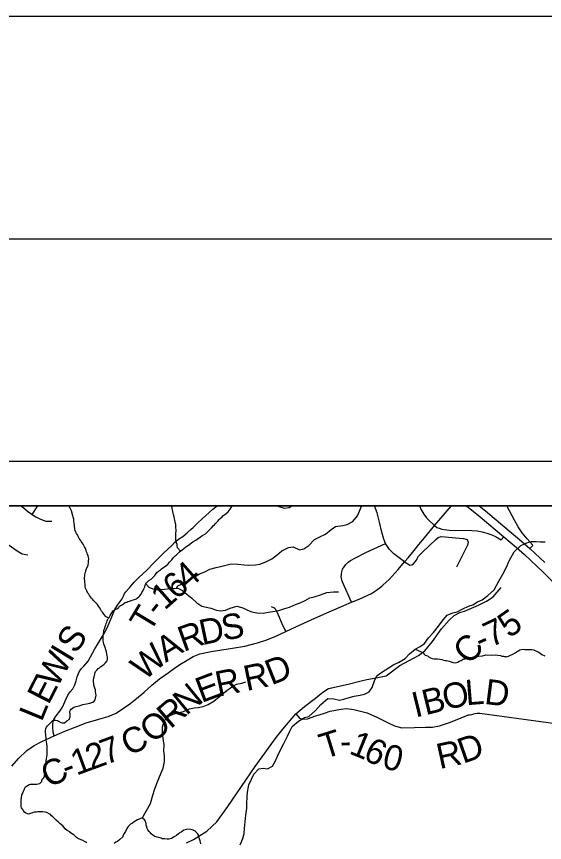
# Model space of a CAD drawing. Extents: x 44.2 to 78.2, y 4.5 to 26.5.
# Drawn here: x 49.173 to 50.361, y 24.644 to 26.501 of the extents above; entities that cross this region are included whole.
import ezdxf

# ---------------------------------------------------------------- set-up
doc = ezdxf.new("R2010")
doc.units = 0
for name, color, linetype in [('GM_X_County_Road', 7, 'Continuous'), ('GM_X_County_Road_Text', 7, 'Continuous'), ('GM_X_Interchange_Ramps', 7, 'Continuous'), ('GM_X_Interstate_Route', 7, 'Continuous'), ('GM_X_Minor_River', 7, 'Continuous'), ('GM_X_Rail_Line', 7, 'Continuous'), ('GM_X_Township_Road', 7, 'Continuous'), ('GM_X_Township_Road_Text', 7, 'Continuous'), ('SH_Border', 7, 'Continuous'), ('SH_Cut_Line', 7, 'Continuous'), ('SH_Data', 7, 'Continuous')]:
    doc.layers.add(name, color=color, linetype=linetype)

msp = doc.modelspace()

# ---------------------------------------------------------------- linework, layer by layer
at = {"layer": 'GM_X_County_Road'}
msp.add_line((50.1134, 25.3565), (50.1514, 25.4014), dxfattribs=at)
for points in [[(50.0459, 25.2748), (50.0543, 25.284), (50.0678, 25.3006), (50.0777, 25.3138), (50.0943, 25.3338), (50.1134, 25.3565)], [(49.9979, 25.2233), (50.0112, 25.2352), (50.0311, 25.2579), (50.0459, 25.2748)], [(49.1626, 24.8156), (49.1774, 24.8328), (49.1961, 24.8509), (49.2125, 24.8619), (49.2302, 24.8712), (49.2575, 24.8838), (49.2819, 24.8942), (49.3048, 24.9037), (49.3297, 24.9129), (49.3579, 24.9214), (49.3794, 24.9275), (49.3884, 24.9308), (49.3968, 24.9351), (49.4136, 24.9459), (49.4275, 24.9562), (49.4432, 24.9682), (49.4601, 24.9824), (49.4771, 24.998), (49.4949, 25.0121), (49.5143, 25.0257), (49.5287, 25.0358), (49.5407, 25.0443), (49.5565, 25.0543), (49.5701, 25.0622), (49.5855, 25.0681), (49.6105, 25.0734), (49.6588, 25.0807), (49.6866, 25.0855), (49.715, 25.0929), (49.736, 25.0999), (49.7561, 25.1082), (49.779, 25.1187), (49.8109, 25.1332), (49.8439, 25.1482), (49.8759, 25.1626), (49.9094, 25.1773), (49.9266, 25.1842), (49.9438, 25.1912), (49.9716, 25.2043), (49.9824, 25.2117), (49.9949, 25.2206), (49.9979, 25.2233)], [(49.5557, 24.6434), (49.5708, 24.6505), (49.6014, 24.6696), (49.6239, 24.6908), (49.6486, 24.7247), (49.71, 24.815), (49.7573, 24.8805), (49.7717, 24.8985), (49.8009, 24.9332), (49.8207, 24.9502), (49.8452, 24.9685), (49.8623, 24.9824), (49.8746, 24.9906), (49.9187, 25.0004), (49.9485, 25.0078), (49.9612, 25.0102), (49.9816, 25.0144), (50.0043, 25.0186), (50.0353, 25.0422), (50.077, 25.0643), (50.0912, 25.0747), (50.109, 25.0963), (50.1286, 25.1243), (50.1461, 25.1437), (50.1571, 25.1546), (50.1699, 25.1609), (50.181, 25.1639), (50.2124, 25.178), (50.2303, 25.1865), (50.2453, 25.1967), (50.2632, 25.2171)]]:
    msp.add_lwpolyline(points, dxfattribs=at)
at = {"layer": 'GM_X_Interchange_Ramps'}
msp.add_line((50.0791, 25.4014), (50.0798, 25.3997), dxfattribs=at)
for points in [[(50.0798, 25.3997), (50.0823, 25.3937), (50.0888, 25.3825), (50.0953, 25.3738), (50.1016, 25.3674), (50.1091, 25.3605), (50.1134, 25.3565)], [(50.3279, 25.3049), (50.3346, 25.3121), (50.3336, 25.3132), (50.3216, 25.3269), (50.3105, 25.3405), (50.3016, 25.3536), (50.2936, 25.3677), (50.2761, 25.4014)], [(50.1134, 25.3565), (50.1181, 25.3526), (50.1233, 25.3505), (50.1293, 25.3485), (50.1465, 25.3462), (50.1975, 25.3454), (50.209, 25.3445), (50.2206, 25.3427), (50.231, 25.3398), (50.2421, 25.3358), (50.2517, 25.3314), (50.263, 25.3248), (50.2688, 25.3317)]]:
    msp.add_lwpolyline(points, dxfattribs=at)
at = {"layer": 'GM_X_Interstate_Route'}
for points in [[(50.1852, 25.4014), (50.2158, 25.376), (50.2688, 25.3317), (50.2974, 25.3075), (50.3157, 25.2913), (50.3584, 25.2515), (50.3899, 25.2199)], [(50.2138, 25.4014), (50.228, 25.3896), (50.2809, 25.3452), (50.3096, 25.321), (50.3279, 25.3049), (50.3611, 25.274)]]:
    msp.add_lwpolyline(points, dxfattribs=at)
at = {"layer": 'GM_X_Minor_River'}
for points in [[(49.3803, 25.1488), (49.3746, 25.1512), (49.3694, 25.1574), (49.3661, 25.162), (49.3643, 25.1643), (49.3625, 25.1674), (49.3596, 25.1721), (49.3577, 25.1751), (49.3548, 25.179), (49.3463, 25.188), (49.3441, 25.191), (49.3419, 25.1934), (49.3393, 25.1965), (49.3375, 25.1992), (49.3353, 25.2023), (49.3334, 25.205), (49.3313, 25.2096), (49.3294, 25.2131), (49.3284, 25.2161), (49.3277, 25.2188), (49.3274, 25.2211), (49.3271, 25.2256), (49.3268, 25.2287), (49.3265, 25.2329), (49.3262, 25.2363), (49.3259, 25.2389), (49.3264, 25.2435), (49.3265, 25.2458), (49.3277, 25.2503), (49.3286, 25.2537), (49.3299, 25.2589), (49.3323, 25.2638), (49.3339, 25.2676), (49.3348, 25.274), (49.3352, 25.2763), (49.3354, 25.2816), (49.3351, 25.285), (49.3344, 25.2892), (49.333, 25.2915), (49.3319, 25.2946), (49.3305, 25.2976), (49.3298, 25.3003), (49.3287, 25.303), (49.3273, 25.3068), (49.3262, 25.3091), (49.3247, 25.3118), (49.3229, 25.3149), (49.3185, 25.3211), (49.3167, 25.3242), (49.3141, 25.328), (49.3127, 25.3307), (49.3116, 25.333), (49.3098, 25.3361), (49.308, 25.3388), (49.3065, 25.3419), (49.3051, 25.3457), (49.3044, 25.3484), (49.3041, 25.3507), (49.3034, 25.3545), (49.3031, 25.3579), (49.3025, 25.3617), (49.3022, 25.367), (49.3016, 25.3712), (49.3002, 25.3758), (49.2999, 25.3785), (49.2963, 25.3899), (49.2938, 25.3957), (49.2909, 25.4014)], [(49.5418, 25.2992), (49.535, 25.3063), (49.534, 25.3116), (49.5341, 25.3139), (49.5327, 25.3177), (49.5323, 25.32), (49.5313, 25.3246), (49.5311, 25.3299), (49.5311, 25.333), (49.5316, 25.336), (49.5317, 25.3394), (49.5322, 25.3451), (49.5319, 25.3477), (49.5316, 25.3512), (49.5317, 25.3534), (49.531, 25.3588), (49.5307, 25.3614), (49.5301, 25.3649), (49.529, 25.3687), (49.5283, 25.3721), (49.5277, 25.3763), (49.5263, 25.3813), (49.5256, 25.3847), (49.5246, 25.3885), (49.5235, 25.392), (49.5232, 25.3954), (49.5222, 25.4007), (49.5221, 25.4014)], [(49.5257, 25.2842), (49.5296, 25.2886), (49.5323, 25.2904), (49.5351, 25.2934), (49.5397, 25.2978), (49.5425, 25.2997), (49.5459, 25.3022), (49.5529, 25.3081), (49.556, 25.3103), (49.5599, 25.3129), (49.563, 25.3151), (49.5665, 25.318), (49.5699, 25.3202), (49.5761, 25.3238), (49.5796, 25.3264), (49.5827, 25.3286), (49.5862, 25.3308), (49.59, 25.3333), (49.5981, 25.3384), (49.602, 25.3417), (49.6067, 25.3473), (49.609, 25.3491), (49.6118, 25.3517), (49.6157, 25.3565), (49.618, 25.3584), (49.62, 25.3606), (49.6231, 25.3639), (49.6258, 25.3665), (49.6286, 25.3706), (49.6313, 25.3724), (49.6352, 25.3761), (49.6367, 25.3784), (49.6391, 25.3798), (49.6445, 25.3842), (49.6488, 25.3879), (49.6515, 25.3905), (49.6538, 25.3935), (49.6566, 25.398), (49.6582, 25.401), (49.6583, 25.4014)], [(49.5331, 25.2158), (49.5359, 25.2209), (49.5509, 25.2279), (49.5613, 25.2345), (49.5713, 25.24), (49.5847, 25.2481), (49.5966, 25.2528), (49.6081, 25.2587), (49.6219, 25.2626), (49.6318, 25.2643), (49.644, 25.2679), (49.6555, 25.2703), (49.671, 25.27), (49.6854, 25.2686), (49.6957, 25.268), (49.7105, 25.2681), (49.7204, 25.2698), (49.7338, 25.2749), (49.7476, 25.2822), (49.7592, 25.2907), (49.7696, 25.3), (49.7846, 25.3073), (49.7953, 25.309), (49.8092, 25.3023), (49.8195, 25.3044), (49.8307, 25.3121), (49.8435, 25.3256), (49.855, 25.3311), (49.8677, 25.3377), (49.8804, 25.3477), (49.8904, 25.3547), (49.9068, 25.3567), (49.9167, 25.3591), (49.9294, 25.3657), (49.9403, 25.3784), (49.9447, 25.3894), (49.9487, 25.4003), (49.9509, 25.4014)], [(49.7577, 25.4014), (49.7607, 25.4002), (49.7747, 25.3961), (49.7861, 25.3974), (49.7922, 25.4014)], [(49.6762, 24.6387), (49.6822, 24.6527), (49.6851, 24.6644), (49.6861, 24.6758), (49.6875, 24.6902), (49.689, 24.7058), (49.6908, 24.7213), (49.691, 24.7312), (49.6918, 24.7476), (49.6927, 24.7574), (49.6953, 24.7737), (49.7013, 24.7862), (49.7068, 24.7978), (49.7177, 24.8098), (49.7276, 24.8115), (49.7375, 24.8094), (49.7486, 24.8153), (49.7545, 24.8258), (49.7601, 24.8382), (49.7688, 24.8567), (49.7744, 24.8669), (49.7827, 24.8834), (49.7875, 24.8944), (49.793, 24.9045), (49.8069, 24.9168), (49.8208, 24.9249), (49.8303, 24.9274), (49.8454, 24.9411), (49.8575, 24.9546), (49.8729, 24.968), (49.8866, 24.9673), (49.8994, 24.964), (49.909, 24.9665), (49.9189, 24.9697), (49.9323, 24.9729), (49.946, 24.9757), (49.9559, 24.9778), (49.9659, 24.9829), (49.973, 24.9926), (49.9786, 25.01), (49.9841, 25.0198), (49.9972, 25.0287), (50.0088, 25.0357), (50.0219, 25.0445), (50.0319, 25.0489), (50.0469, 25.0581), (50.0569, 25.0682), (50.0697, 25.0786), (50.0808, 25.0848), (50.0908, 25.0915), (50.0995, 25.1042), (50.1107, 25.1166), (50.122, 25.1308), (50.1326, 25.145), (50.1415, 25.1551), (50.1542, 25.1602), (50.1645, 25.1627), (50.1768, 25.1697), (50.1894, 25.1755), (50.1994, 25.1783), (50.2101, 25.185), (50.2201, 25.1897), (50.2332, 25.1994), (50.2472, 25.2124), (50.2582, 25.2319), (50.2669, 25.2474), (50.2752, 25.2632), (50.2812, 25.2775), (50.2926, 25.2978), (50.3077, 25.312), (50.3211, 25.3182), (50.3315, 25.321), (50.3417, 25.3212), (50.3516, 25.3202), (50.3622, 25.3204)], [(49.3072, 24.9496), (49.3137, 24.9513), (49.3221, 24.9541), (49.3305, 24.9562), (49.3381, 24.9575), (49.345, 24.9596), (49.3478, 24.9618), (49.3497, 24.9648), (49.351, 24.9689), (49.3514, 24.972), (49.3519, 24.9746), (49.3516, 24.9792), (49.351, 24.9834), (49.3503, 24.9872), (49.3493, 24.991), (49.3485, 24.9933), (49.3471, 24.9975), (49.3468, 24.9998), (49.3462, 25.0066), (49.3463, 25.0097), (49.3476, 25.0168), (49.3498, 25.0263), (49.351, 25.0285), (49.3541, 25.0326), (49.3565, 25.0352), (49.3595, 25.037), (49.3623, 25.0396), (49.3661, 25.0421), (49.37, 25.0451), (49.3735, 25.0484), (49.3767, 25.0529), (49.3779, 25.0555), (49.3775, 25.0582), (49.3776, 25.0612), (49.3769, 25.0642), (49.3763, 25.0677), (49.3753, 25.0726), (49.3739, 25.0772), (49.3721, 25.0822), (49.3707, 25.0864), (49.3693, 25.091), (49.3686, 25.0937), (49.3679, 25.0967), (49.3681, 25.1035), (49.3678, 25.1066), (49.3682, 25.11), (49.3683, 25.1123), (49.3687, 25.1149), (49.3692, 25.1172), (49.3697, 25.1217), (49.3713, 25.1258), (49.3725, 25.1296), (49.3738, 25.1337), (49.375, 25.1367), (49.3762, 25.1398), (49.377, 25.1424), (49.3778, 25.1446), (49.3794, 25.1476), (49.3814, 25.1502), (49.3834, 25.1547), (49.3874, 25.1603), (49.3913, 25.1655), (49.3955, 25.1677), (49.3986, 25.1695), (49.4029, 25.1724), (49.4048, 25.1754), (49.4072, 25.1769), (49.4095, 25.178), (49.4137, 25.1809), (49.4172, 25.1834), (49.421, 25.1845), (49.4233, 25.1856), (49.4268, 25.1866), (49.4329, 25.1887), (49.4383, 25.1905), (49.4425, 25.1923), (49.4452, 25.1941), (49.4479, 25.1963), (49.4503, 25.1989), (49.453, 25.2022), (49.455, 25.206), (49.4578, 25.2105), (49.4594, 25.2142), (49.4614, 25.2187), (49.4626, 25.2217), (49.4634, 25.2243), (49.4654, 25.2277), (49.4709, 25.2329), (49.4755, 25.2365), (49.4798, 25.2402), (49.4841, 25.2443), (49.4888, 25.251), (49.4923, 25.2539), (49.4969, 25.2572), (49.4993, 25.2591), (49.5043, 25.2635), (49.5078, 25.2653), (49.514, 25.2708), (49.5171, 25.2741), (49.5226, 25.2797), (49.5257, 25.2842)], [(49.4642, 25.2256), (49.4709, 25.218), (49.483, 25.2128), (49.4993, 25.2129), (49.5126, 25.2142), (49.5252, 25.2154), (49.5358, 25.216), (49.5463, 25.2105), (49.5564, 25.2027), (49.5676, 25.1937), (49.5788, 25.1832), (49.5897, 25.1758), (49.6003, 25.1729), (49.6101, 25.1708), (49.6225, 25.1668), (49.6324, 25.1651), (49.6434, 25.1667), (49.6538, 25.1707), (49.6683, 25.1754), (49.6823, 25.1717), (49.6924, 25.1665), (49.7026, 25.1625), (49.7132, 25.1604), (49.7276, 25.1598), (49.7387, 25.1622), (49.7493, 25.1635), (49.7627, 25.1656), (49.7768, 25.1702), (49.7868, 25.1735), (49.8006, 25.1789), (49.8113, 25.1832), (49.822, 25.1884), (49.8324, 25.1939), (49.8427, 25.1967), (49.8568, 25.2006), (49.871, 25.2064), (49.8859, 25.2076), (49.8976, 25.2074)], [(50.0701, 25.0788), (50.0874, 25.0707), (50.0896, 25.0676), (50.0925, 25.0656), (50.0948, 25.0648), (50.0989, 25.0628), (50.1015, 25.0608), (50.1042, 25.0592), (50.1079, 25.0576), (50.1121, 25.0571), (50.1166, 25.0574), (50.1201, 25.0569), (50.125, 25.0564), (50.1295, 25.0555), (50.1336, 25.0539), (50.1363, 25.0534), (50.1397, 25.053), (50.1431, 25.0529), (50.1465, 25.052), (50.1506, 25.05), (50.1548, 25.0488), (50.1605, 25.0483), (50.1654, 25.0493), (50.1685, 25.0515), (50.1728, 25.0536), (50.1774, 25.0562), (50.1797, 25.0569), (50.1824, 25.0572), (50.1862, 25.0582), (50.1942, 25.0599), (50.2011, 25.0612), (50.2068, 25.0618), (50.2098, 25.0625), (50.2125, 25.0632), (50.2209, 25.0641), (50.2262, 25.0651), (50.2285, 25.0658), (50.2411, 25.0655), (50.2494, 25.0657), (50.2555, 25.0655), (50.2619, 25.0642), (50.2645, 25.0634), (50.268, 25.0629), (50.2702, 25.0625), (50.2736, 25.062), (50.2759, 25.0619), (50.2794, 25.063), (50.2843, 25.0651), (50.2897, 25.0676), (50.2944, 25.0706), (50.2994, 25.0738), (50.3025, 25.0757), (50.3052, 25.0771), (50.3078, 25.0782), (50.3132, 25.0784), (50.3166, 25.0783), (50.3223, 25.0778), (50.3249, 25.0781), (50.3318, 25.0779), (50.3359, 25.0771), (50.3427, 25.0742), (50.348, 25.0722), (50.3517, 25.0691), (50.3543, 25.0671), (50.361, 25.0635)], [(49.4565, 24.6984), (49.4584, 24.7038), (49.4643, 24.7147), (49.4742, 24.732), (49.4799, 24.7506), (49.4835, 24.7623), (49.4884, 24.777), (49.4932, 24.7876), (49.4984, 24.8004), (49.5032, 24.8113), (49.5057, 24.8261), (49.5056, 24.8386), (49.5047, 24.8504), (49.505, 24.8637), (49.5037, 24.8737), (49.5024, 24.8836), (49.5011, 24.8935), (49.5017, 24.9041), (49.5053, 24.9174), (49.5178, 24.9297), (49.5277, 24.9333), (49.5388, 24.9361), (49.5487, 24.9389), (49.5621, 24.9444), (49.5724, 24.9468), (49.5819, 24.9474), (49.593, 24.9502), (49.6037, 24.9546), (49.6168, 24.9616), (49.6299, 24.9723), (49.6431, 24.9839), (49.6573, 24.9942), (49.6677, 24.9997), (49.6795, 25.0022), (49.6891, 25.0054)], [(49.3018, 24.6614), (49.2943, 24.6654), (49.2928, 24.6681), (49.2872, 24.6709), (49.2827, 24.6745), (49.2772, 24.6818), (49.2712, 24.6858), (49.2671, 24.6897), (49.2623, 24.6943), (49.2583, 24.6982), (49.2545, 24.7017), (49.2519, 24.7041), (49.2494, 24.7068), (49.2464, 24.7088), (49.2411, 24.7116), (49.237, 24.7124), (49.2317, 24.713), (49.2275, 24.7127), (49.221, 24.7129), (49.218, 24.7126), (49.2153, 24.7123), (49.213, 24.7119), (49.2092, 24.7109), (49.2069, 24.7098), (49.2042, 24.7091), (49.2019, 24.7088), (49.1996, 24.7081), (49.1974, 24.7086), (49.194, 24.7098), (49.191, 24.7125), (49.1884, 24.7152), (49.1881, 24.7175), (49.1859, 24.7195), (49.184, 24.7222), (49.1837, 24.7248), (49.1835, 24.7328), (49.1838, 24.7412), (49.1842, 24.7438), (49.1851, 24.751), (49.1863, 24.7532), (49.1875, 24.7559), (49.1888, 24.7592), (49.1904, 24.7626), (49.1924, 24.7682), (49.1947, 24.7701), (49.1998, 24.7737), (49.2044, 24.7751), (49.207, 24.7754), (49.2146, 24.7752), (49.2188, 24.7755), (49.2215, 24.7758), (49.2253, 24.7769), (49.2276, 24.7787), (49.2296, 24.7813), (49.2301, 24.7843), (49.232, 24.7869), (49.2344, 24.7895), (49.2356, 24.7933), (49.2369, 24.7997), (49.2374, 24.8042), (49.2382, 24.8076), (49.2387, 24.8126), (49.2392, 24.8148), (49.2393, 24.8197), (49.2399, 24.8266), (49.2404, 24.8319), (49.2413, 24.8364), (49.2417, 24.8409), (49.2422, 24.8568), (49.2419, 24.861), (49.2412, 24.8656), (49.2406, 24.8702), (49.24, 24.8751), (49.2397, 24.8793), (49.2387, 24.8843), (49.2381, 24.8926), (49.2382, 24.8964), (49.2391, 24.8998), (49.2407, 24.9035), (49.2427, 24.9065), (49.2469, 24.911), (49.2547, 24.918), (49.2586, 24.9194), (49.2612, 24.9193), (49.2654, 24.9181), (49.2676, 24.9169), (49.2725, 24.9141), (49.2759, 24.9132), (49.2781, 24.9128), (49.2812, 24.9131), (49.2859, 24.9175), (49.2912, 24.9204), (49.2933, 24.9268), (49.2938, 24.9302), (49.2935, 24.9336), (49.2932, 24.9359), (49.2928, 24.9386), (49.2944, 24.9416), (49.296, 24.9438), (49.3018, 24.9482), (49.3072, 24.9496)], [(49.5876, 24.641), (49.5866, 24.6449), (49.5859, 24.6475), (49.5856, 24.6498), (49.5849, 24.6521), (49.5842, 24.6548), (49.582, 24.6602), (49.5798, 24.664), (49.578, 24.6667), (49.5743, 24.6702), (49.5683, 24.6727), (49.5649, 24.6731), (49.5584, 24.6737), (49.555, 24.6734), (49.5496, 24.6716), (49.5454, 24.6691), (49.5431, 24.6673), (49.5396, 24.6654), (49.5373, 24.6636), (49.5326, 24.6596), (49.5276, 24.657), (49.5253, 24.6556), (49.5218, 24.653), (49.5184, 24.6523), (49.5153, 24.6517), (49.5115, 24.6514), (49.5066, 24.6519), (49.5028, 24.6524), (49.5005, 24.6524), (49.4983, 24.6536), (49.4923, 24.6549), (49.4843, 24.6578), (49.4821, 24.659), (49.4799, 24.6606), (49.4761, 24.6633), (49.4736, 24.6664), (49.471, 24.6691), (49.4684, 24.6726), (49.467, 24.6757), (49.4659, 24.6791), (49.4649, 24.6833), (49.4649, 24.6864), (49.4639, 24.6891), (49.4628, 24.6921), (49.4606, 24.6952), (49.4565, 24.6984), (49.4539, 24.6984), (49.4516, 24.6981), (49.4473, 24.6959), (49.445, 24.6949), (49.4416, 24.6931), (49.4377, 24.6905), (49.4338, 24.6876), (49.4296, 24.685), (49.4261, 24.6825), (49.4241, 24.6802), (49.4226, 24.6776), (49.421, 24.6754), (49.4182, 24.669), (49.415, 24.6642), (49.4122, 24.6589), (49.4122, 24.6566), (49.4055, 24.6504), (49.4001, 24.646), (49.3967, 24.6445), (49.3924, 24.642)], [(49.3313, 24.6436), (49.3291, 24.6448), (49.3204, 24.6496), (49.3122, 24.6524), (49.3077, 24.6552), (49.3018, 24.6614)]]:
    msp.add_lwpolyline(points, dxfattribs=at)
at = {"layer": 'GM_X_Rail_Line'}
msp.add_lwpolyline([(53.1359, 25.4014), (48.0411, 25.4014), (48.0269, 25.3874), (47.9997, 25.3285), (47.9902, 25.2922), (47.9948, 25.2567), (48.016, 25.2302), (48.076, 25.2002), (48.1616, 25.1532), (48.1984, 25.1081), (48.2145, 25.0522), (48.3347, 24.571)], dxfattribs=at)
at = {"layer": 'GM_X_Township_Road'}
msp.add_line((49.2081, 25.3813), (49.2208, 25.4014), dxfattribs=at)
for points in [[(49.1825, 25.4014), (49.1863, 25.3986), (49.1977, 25.3893), (49.2081, 25.3813), (49.2166, 25.376), (49.2269, 25.3713), (49.2391, 25.3665), (49.2524, 25.3668)], [(49.5656, 25.3483), (49.5702, 25.3526), (49.5817, 25.3636), (49.5978, 25.3787), (49.6147, 25.3939), (49.624, 25.4014)], [(50.0459, 25.2748), (50.0218, 25.2932), (50.0118, 25.303), (50.0032, 25.3165), (49.9992, 25.326), (49.9944, 25.3416), (49.9891, 25.3642), (49.9844, 25.3856), (49.9783, 25.4014)], [(48.9772, 25.3347), (49.0121, 25.3329), (49.0442, 25.3314), (49.0741, 25.3403), (49.0918, 25.3447), (49.1084, 25.3425), (49.1372, 25.3251), (49.1543, 25.3142), (49.1745, 25.2997), (49.1856, 25.293), (49.1985, 25.2908)], [(49.427, 25.217), (49.4375, 25.2296), (49.4481, 25.24), (49.4659, 25.2566), (49.482, 25.2728), (49.5047, 25.2953), (49.522, 25.312), (49.5287, 25.3189), (49.5377, 25.3263), (49.5471, 25.3324), (49.5571, 25.3405), (49.5656, 25.3483)], [(49.9266, 25.1842), (49.9078, 25.2267), (49.9047, 25.2343), (49.9038, 25.2385), (49.9036, 25.2421), (49.904, 25.2457), (49.904, 25.2481), (49.9047, 25.2524), (49.9063, 25.2586), (49.9099, 25.2642), (49.9135, 25.2689), (49.9188, 25.2743), (49.924, 25.2784), (49.9358, 25.2842), (49.9589, 25.2962), (50.0032, 25.3165)], [(50.0459, 25.2748), (50.0531, 25.2704), (50.0578, 25.268), (50.0619, 25.2682), (50.0656, 25.2707), (50.0716, 25.278), (50.0773, 25.288), (50.0858, 25.2971), (50.1155, 25.3248), (50.1213, 25.3299), (50.1279, 25.3318), (50.1371, 25.3316), (50.1602, 25.3294), (50.1786, 25.3277), (50.1869, 25.3251), (50.1891, 25.3192), (50.1877, 25.3129), (50.1628, 25.2635)], [(49.2575, 24.8838), (49.2556, 24.8921), (49.2545, 24.9027), (49.2544, 24.9119), (49.257, 24.9209), (49.2618, 24.9288), (49.2701, 24.9395), (49.2761, 24.9485), (49.2844, 24.9671), (49.2882, 24.975), (49.2938, 24.9827), (49.2993, 24.9899), (49.3039, 24.9986), (49.3068, 25.0078), (49.3096, 25.0164), (49.3139, 25.0276), (49.3181, 25.0342), (49.3241, 25.0407), (49.3338, 25.0519), (49.3495, 25.0796), (49.3658, 25.1062), (49.3721, 25.1179), (49.3788, 25.1317), (49.3877, 25.1515), (49.3944, 25.1682), (49.4002, 25.1777), (49.4059, 25.1858), (49.411, 25.192), (49.4134, 25.198), (49.4156, 25.2036), (49.419, 25.208), (49.4249, 25.2145), (49.427, 25.217)], [(49.779, 25.1187), (49.7706, 25.1357), (49.7624, 25.1551), (49.7563, 25.1676), (49.7537, 25.1705), (49.7514, 25.1718), (49.7466, 25.1738)], [(49.8009, 24.9332), (49.8093, 24.9237), (49.8173, 24.9211), (49.8274, 24.9222), (49.8459, 24.9286), (49.8635, 24.9344), (49.8786, 24.9392), (49.8905, 24.9415), (49.9023, 24.9438), (49.9151, 24.945), (49.9317, 24.9433), (49.9615, 24.9358), (49.9834, 24.9255), (50.0071, 24.9142), (50.0234, 24.9066), (50.04, 24.9015), (50.0684, 24.9024), (50.0929, 24.9033), (50.109, 24.9032), (50.1243, 24.9063), (50.1491, 24.9149), (50.1732, 24.9243), (50.19, 24.9311), (50.192, 24.9314)], [(50.192, 24.9314), (50.1972, 24.9321), (50.2014, 24.9332), (50.2048, 24.9342), (50.209, 24.9349), (50.2151, 24.9352), (50.4016, 24.909), (50.4644, 24.8987), (50.534, 24.8876)]]:
    msp.add_lwpolyline(points, dxfattribs=at)
at = {"layer": 'SH_Border'}
msp.add_lwpolyline([(45.7359, 26.0014), (77.7359, 26.0014), (77.7359, 5.0014), (45.7359, 5.0014)], close=True, dxfattribs=at)
at = {"layer": 'SH_Cut_Line'}
msp.add_lwpolyline([(44.2359, 4.5014), (78.2359, 4.5014), (78.2359, 26.5014), (44.2359, 26.5014)], close=True, dxfattribs=at)
msp.add_lwpolyline([(53.1359, 25.4014), (48.0411, 25.4014), (48.0269, 25.3874), (47.9997, 25.3285), (47.9902, 25.2922), (47.9948, 25.2567), (48.016, 25.2302), (48.076, 25.2002), (48.1616, 25.1532), (48.1984, 25.1081), (48.2145, 25.0522), (48.3347, 24.571)], dxfattribs=at)
at = {"layer": 'SH_Data'}
for p, q in [((46.2359, 25.5014), (53.2359, 25.5014)), ((46.3359, 25.4014), (53.1359, 25.4014))]:
    msp.add_line(p, q, dxfattribs=at)

# ---------------------------------------------------------------- texts
at = {"layer": 'GM_X_County_Road_Text'}
for s, rotation, p in [('5', 35.0619, (50.2811, 25.1022)), ('D', 11.895, (49.5905, 25.0876)), ('S', 10.1888, (49.6389, 25.0978)), ('7', 25.0374, (50.24, 25.082)), ('R', 19.8471, (49.5486, 25.0723)), ('A', 31.1655, (49.5085, 25.0477)), ('C', 47.1532, (50.1909, 25.0413)), ('W', 40.7979, (49.4607, 25.0062)), ('-', 24.0893, (50.2178, 25.072)), ('D', 21.6843, (49.7463, 24.997)), ('R', 11.7514, (49.6903, 24.9844)), ('E', 20.5184, (49.5889, 24.9573)), ('R', 11.6283, (49.6265, 24.9716)), ('N', 39.4324, (49.5546, 24.9281)), ('R', 40.6405, (49.5194, 24.8979)), ('O', 38.6705, (49.4787, 24.8653)), ('C', 26.0466, (49.4253, 24.8375)), ('2', 20.1845, (49.3406, 24.8062)), ('7', 20.1467, (49.3734, 24.8183)), ('1', 20.3459, (49.3078, 24.7941)), ('C', 26.1426, (49.2455, 24.7658)), ('-', 20.8548, (49.2861, 24.7858))]:
    msp.add_text(s, height=0.0568, rotation=rotation, dxfattribs=at).set_placement(p)
at = {"layer": 'GM_X_Township_Road_Text'}
for s, rotation, p in [('4', 41.2683, (49.5595, 25.2113)), ('6', 40.6538, (49.5324, 25.1881)), ('1', 41.4468, (49.5063, 25.165)), ('T', 59.0032, (49.4731, 25.1137)), ('-', 52.0778, (49.4939, 25.1487)), ('S', 56.4523, (49.3068, 25.0661)), ('W', 61.8002, (49.2643, 24.9894)), ('I', 58.5837, (49.2949, 25.0467)), ('E', 62.9021, (49.245, 24.9518)), ('O', 13.4708, (50.1381, 24.9412)), ('L', 4.7024, (50.1845, 24.9525)), ('D', 352.7132, (50.2237, 24.956)), ('I', 13.7523, (50.0702, 24.9246)), ('B', 13.7549, (50.0929, 24.9301)), ('L', 67.7322, (49.2295, 24.9137)), ('T', 17.2165, (49.8647, 24.8314)), ('1', 337.8121, (49.9185, 24.845)), ('6', 333.9446, (49.95, 24.8322)), ('R', 12.2629, (50.1246, 24.8089)), ('D', 19.2349, (50.1773, 24.8208)), ('-', 1.4598, (49.9012, 24.8433)), ('0', 345.2011, (49.9928, 24.8126))]:
    msp.add_text(s, height=0.0568, rotation=rotation, dxfattribs=at).set_placement(p)

doc.saveas('drawing.dxf')
